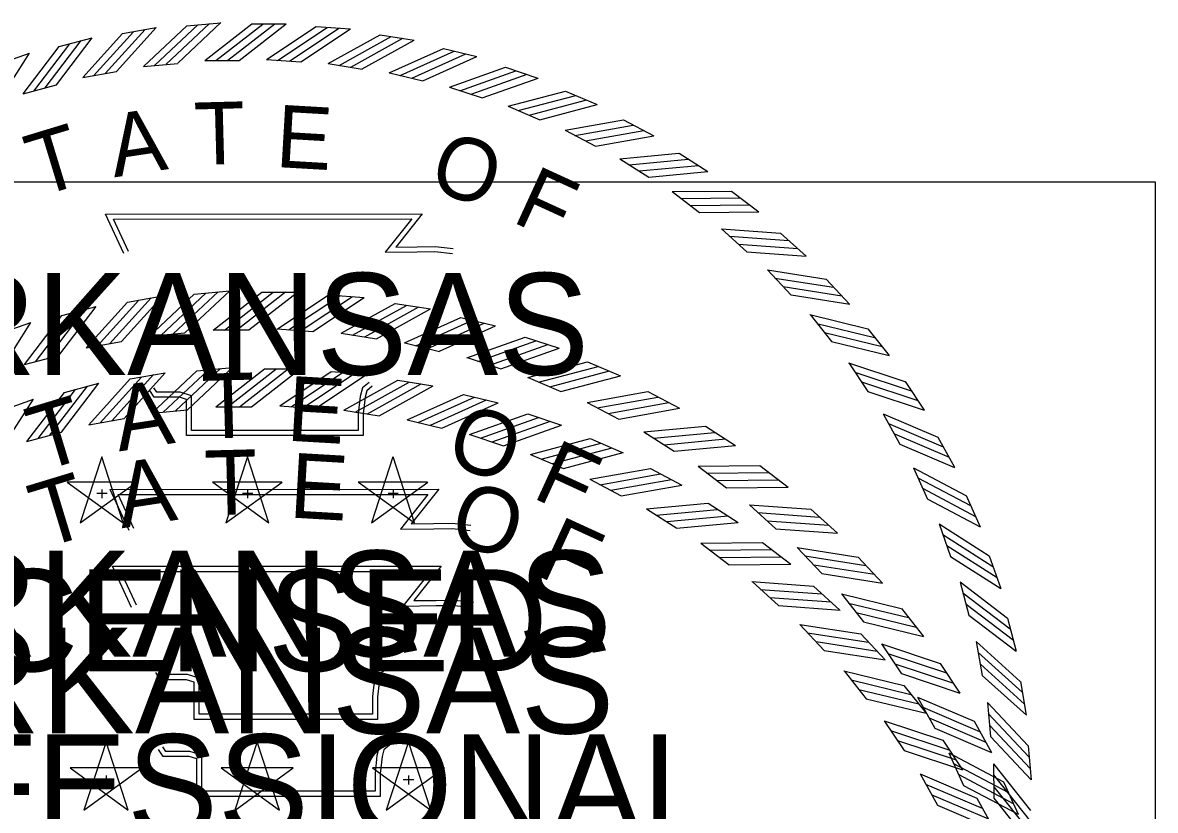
# Model space of a CAD drawing. Extents: x 0 to 1228740, y 0 to 152440.
# Drawn here: x 31.694 to 33.423, y 24.476 to 25.678 of the extents above; entities that cross this region are included whole.
import ezdxf

# ---------------------------------------------------------------- set-up
doc = ezdxf.new("R2010")
doc.units = 0
for name, color, linetype in [('R_No Plot', 7, 'Continuous'), ('STAMP_LKM', 7, 'Continuous'), ('STAMP_PP', 7, 'Continuous'), ('STAMP_SPT', 7, 'Continuous')]:
    doc.layers.add(name, color=color, linetype=linetype)

msp = doc.modelspace()

# ---------------------------------------------------------------- linework, layer by layer
at = {"layer": 'R_No Plot'}
msp.add_lwpolyline([(30.6731, 25.4352), (33.4231, 25.4352), (33.4231, 22.6852), (30.6731, 22.6852)], close=True, dxfattribs=at)
at = {"layer": 'STAMP_LKM'}
for p, q in [((31.8544, 25.2516), (31.9079, 25.2611)), ((31.9562, 25.2638), (32.0104, 25.2688)), ((32.0592, 25.2669), (32.1136, 25.2669)), ((32.1611, 25.2628), (32.2154, 25.2588)), ((31.7539, 25.2311), (31.8065, 25.245)), ((32.2628, 25.2496), (32.3166, 25.2411)), ((32.3631, 25.228), (32.416, 25.2151)), ((31.6554, 25.2024), (31.7067, 25.2205)), ((31.985, 25.209), (32.0395, 25.209)), ((32.0828, 25.2105), (32.1372, 25.2065)), ((31.7913, 25.1817), (31.845, 25.1912)), ((31.8876, 25.1994), (31.9419, 25.2044)), ((32.1805, 25.2039), (32.2344, 25.1954)), ((32.4613, 25.1982), (32.5129, 25.181)), ((32.2773, 25.1893), (32.3303, 25.1764)), ((31.6968, 25.1562), (31.7495, 25.1701)), ((32.3725, 25.1668), (32.4243, 25.1495)), ((32.5566, 25.1605), (32.6066, 25.1391)), ((32.4656, 25.1364), (32.5157, 25.115)), ((32.6485, 25.115), (32.6966, 25.0895)), ((32.5558, 25.0985), (32.604, 25.073)), ((32.6426, 25.0533), (32.6885, 25.0239)), ((32.7364, 25.062), (32.7822, 25.0327)), ((32.7254, 25.001), (32.7687, 24.9679)), ((32.8195, 25.002), (32.8628, 24.969)), ((32.8035, 24.9421), (32.844, 24.9056)), ((32.8974, 24.9353), (32.9378, 24.8988)), ((32.8766, 24.877), (32.9139, 24.8372)), ((32.9696, 24.8624), (33.0068, 24.8227)), ((32.944, 24.806), (32.9779, 24.7633)), ((33.0355, 24.7838), (33.0693, 24.7412)), ((33.0053, 24.7297), (33.0355, 24.6843)), ((33.0946, 24.7001), (33.1248, 24.6548)), ((33.0601, 24.6486), (33.0865, 24.6009)), ((33.1467, 24.6117), (33.173, 24.5641)), ((31.8215, 24.5804), (31.7874, 24.476)), ((31.8554, 24.476), (31.8215, 24.5805)), ((32.0523, 24.5804), (32.0182, 24.476)), ((32.0862, 24.476), (32.0523, 24.5805)), ((32.283, 24.5804), (32.249, 24.476)), ((32.317, 24.476), (32.2831, 24.5805)), ((33.108, 24.5633), (33.1304, 24.5135)), ((31.8763, 24.5405), (31.7665, 24.5406)), ((31.7666, 24.5405), (31.8554, 24.4759)), ((31.7876, 24.476), (31.8765, 24.5405)), ((32.1071, 24.5405), (31.9973, 24.5406)), ((31.9974, 24.5405), (32.0862, 24.4759)), ((32.0183, 24.476), (32.1073, 24.5405)), ((32.3379, 24.5405), (32.2281, 24.5406)), ((32.2282, 24.5405), (32.317, 24.4759)), ((32.2491, 24.476), (32.338, 24.5405)), ((31.8137, 24.523), (31.83, 24.523)), ((31.8216, 24.5288), (31.8216, 24.5151)), ((32.0444, 24.523), (32.0608, 24.523)), ((32.0524, 24.5288), (32.0524, 24.5151)), ((32.2752, 24.523), (32.2915, 24.523)), ((32.2831, 24.5288), (32.2831, 24.5151)), ((33.1913, 24.5193), (33.2136, 24.4697))]:
    msp.add_line(p, q, dxfattribs=at)
for points in [[(31.8449, 25.1912), (31.908, 25.2611)], [(31.8875, 25.1993), (31.9561, 25.2638)], [(31.905, 25.2007), (31.9736, 25.2652)], [(31.9238, 25.2029), (31.9924, 25.2674)], [(31.9418, 25.2044), (32.0104, 25.2689)], [(31.9849, 25.2089), (32.0592, 25.2668)], [(32.0024, 25.2087), (32.0767, 25.2666)], [(32.0213, 25.2092), (32.0956, 25.2671)], [(32.0395, 25.209), (32.1137, 25.2669)], [(32.0828, 25.2104), (32.1611, 25.2627)], [(32.1002, 25.209), (32.1785, 25.2613)], [(32.1191, 25.208), (32.1974, 25.2603)], [(31.7495, 25.1701), (31.8065, 25.245)], [(31.7912, 25.1817), (31.8543, 25.2516)], [(31.8085, 25.1846), (31.8716, 25.2545)], [(31.8271, 25.1883), (31.8901, 25.2582)], [(32.1372, 25.2065), (32.2155, 25.2588)], [(32.1804, 25.2039), (32.2628, 25.2495)], [(32.1977, 25.201), (32.28, 25.2466)], [(32.2164, 25.1985), (32.2988, 25.2441)], [(31.6968, 25.1562), (31.7538, 25.231)], [(31.7137, 25.1605), (31.7708, 25.2353)], [(31.7319, 25.1657), (31.789, 25.2406)], [(32.2343, 25.1955), (32.3166, 25.2411)], [(32.2772, 25.1893), (32.363, 25.228)], [(31.6561, 25.1412), (31.7068, 25.2205)], [(32.2942, 25.185), (32.38, 25.2237)], [(32.3126, 25.1809), (32.3985, 25.2196)], [(32.3302, 25.1765), (32.416, 25.2152)], [(32.3724, 25.1667), (32.4612, 25.1982)], [(32.389, 25.1611), (32.4777, 25.1925)], [(32.4071, 25.1555), (32.4958, 25.187)], [(32.4242, 25.1496), (32.5129, 25.1811)], [(32.4655, 25.1364), (32.5565, 25.1605)], [(32.4815, 25.1294), (32.5726, 25.1534)], [(32.4991, 25.1223), (32.5901, 25.1464)], [(32.5157, 25.1151), (32.6067, 25.1391)], [(32.5557, 25.0985), (32.6484, 25.115)], [(32.5711, 25.0902), (32.6638, 25.1066)], [(32.588, 25.0817), (32.6807, 25.0981)], [(32.604, 25.0731), (32.6967, 25.0895)], [(32.6425, 25.0533), (32.7363, 25.062)], [(32.6572, 25.0437), (32.7509, 25.0524)], [(32.6733, 25.0339), (32.7671, 25.0426)], [(32.6885, 25.024), (32.7822, 25.0327)], [(32.7253, 25.001), (32.8194, 25.002)], [(32.7391, 24.9903), (32.8332, 24.9912)], [(32.7544, 24.9791), (32.8485, 24.9801)], [(32.7687, 24.968), (32.8628, 24.969)], [(31.8565, 24.9027), (31.8275, 24.9655), (32.3293, 24.9658), (32.2874, 24.9131), (32.3215, 24.9136), (32.3499, 24.9139), (32.3784, 24.9108)], [(31.8637, 24.906), (31.8399, 24.9576), (32.3128, 24.9579), (32.2707, 24.905), (32.3216, 24.9056), (32.3496, 24.906), (32.3775, 24.9029)], [(32.8035, 24.9421), (32.8973, 24.9353)], [(32.8163, 24.9303), (32.9102, 24.9235)], [(32.8306, 24.9179), (32.9245, 24.9111)], [(32.844, 24.9056), (32.9379, 24.8988)], [(32.8765, 24.877), (32.9695, 24.8624)], [(32.8883, 24.8641), (32.9814, 24.8496)], [(32.9016, 24.8506), (32.9946, 24.8361)], [(32.9139, 24.8373), (33.0069, 24.8227)], [(32.9439, 24.806), (33.0354, 24.7839)], [(32.9546, 24.7922), (33.0461, 24.77)], [(32.9667, 24.7777), (33.0582, 24.7555)], [(32.9779, 24.7634), (33.0693, 24.7412)], [(33.0052, 24.7297), (33.0946, 24.7001)], [(33.0148, 24.7151), (33.1041, 24.6854)], [(32.2502, 24.6924), (32.2417, 24.6855), (32.2388, 24.6751), (32.236, 24.649), (32.236, 24.6144), (31.9559, 24.6144), (31.9559, 24.6612), (31.9559, 24.6716), (31.9445, 24.6751), (31.9047, 24.6751), (31.8976, 24.6859)], [(32.2452, 24.6986), (32.2347, 24.69), (32.231, 24.6765), (32.2281, 24.6495), (32.2281, 24.6223), (31.9638, 24.6223), (31.9638, 24.6612), (31.9638, 24.6775), (31.9457, 24.683), (31.909, 24.683), (31.9042, 24.6902)], [(33.0256, 24.6996), (33.115, 24.6699)], [(33.0355, 24.6844), (33.1249, 24.6548)], [(33.06, 24.6487), (33.1466, 24.6117)], [(33.0683, 24.6333), (33.1549, 24.5963)], [(33.0779, 24.6169), (33.1645, 24.58)], [(33.0865, 24.601), (33.1731, 24.564)], [(33.1079, 24.5633), (33.1912, 24.5194)], [(33.115, 24.5473), (33.1982, 24.5033)], [(33.1231, 24.5302), (33.2063, 24.4863)], [(33.1304, 24.5136), (33.2136, 24.4697)]]:
    msp.add_lwpolyline(points, dxfattribs=at)
at = {"layer": 'STAMP_PP'}
for p, q in [((31.9447, 25.6733), (31.9968, 25.6781)), ((32.0439, 25.6762), (32.0963, 25.6762)), ((31.8466, 25.6616), (31.8982, 25.6707)), ((32.142, 25.6723), (32.1943, 25.6685)), ((32.24, 25.6596), (32.2918, 25.6514)), ((31.7498, 25.6418), (31.8005, 25.6551)), ((31.655, 25.6141), (31.7044, 25.6316)), ((32.3366, 25.6388), (32.3875, 25.6264)), ((31.8786, 25.6112), (31.9309, 25.616)), ((31.9724, 25.6205), (32.0249, 25.6205)), ((32.0666, 25.6219), (32.119, 25.6181)), ((32.1607, 25.6156), (32.2126, 25.6074)), ((32.4311, 25.6101), (32.4808, 25.5936)), ((31.7858, 25.5943), (31.8376, 25.6034)), ((32.2539, 25.6016), (32.3049, 25.5891)), ((31.6948, 25.5697), (31.7456, 25.5831)), ((32.3456, 25.5798), (32.3955, 25.5632)), ((32.5229, 25.5738), (32.5711, 25.5532)), ((32.4353, 25.5506), (32.4836, 25.53)), ((32.6115, 25.5299), (32.6578, 25.5054)), ((32.5222, 25.5141), (32.5686, 25.4895)), ((32.6058, 25.4705), (32.65, 25.4422)), ((32.6961, 25.4789), (32.7402, 25.4507)), ((32.6855, 25.4202), (32.7272, 25.3883)), ((32.7762, 25.4211), (32.8178, 25.3893)), ((32.7608, 25.3635), (32.7997, 25.3283)), ((32.8512, 25.3569), (32.8901, 25.3218)), ((32.8311, 25.3007), (32.867, 25.2624)), ((32.9207, 25.2867), (32.9565, 25.2485)), ((32.896, 25.2324), (32.9287, 25.1912)), ((32.9841, 25.211), (33.0167, 25.17)), ((32.9551, 25.1589), (32.9842, 25.1152)), ((33.0411, 25.1303), (33.0702, 25.0867)), ((33.0079, 25.0808), (33.0333, 25.0348)), ((33.0913, 25.0452), (33.1166, 24.9994)), ((31.8149, 25.0151), (31.7821, 24.9145)), ((31.8476, 24.9145), (31.815, 25.0152)), ((32.0372, 25.0151), (32.0044, 24.9145)), ((32.0698, 24.9145), (32.0372, 25.0152)), ((32.2594, 25.0151), (32.2267, 24.9145)), ((32.2921, 24.9145), (32.2595, 25.0152)), ((33.054, 24.9986), (33.0755, 24.9507)), ((31.8678, 24.9767), (31.762, 24.9768)), ((31.7621, 24.9767), (31.8476, 24.9144)), ((31.7822, 24.9145), (31.8679, 24.9766)), ((32.09, 24.9767), (31.9842, 24.9768)), ((31.9843, 24.9767), (32.0699, 24.9144)), ((32.0045, 24.9145), (32.0902, 24.9766)), ((32.3123, 24.9767), (32.2065, 24.9768)), ((32.2066, 24.9767), (32.2921, 24.9144)), ((32.2268, 24.9145), (32.3124, 24.9766)), ((31.8074, 24.9598), (31.8231, 24.9598)), ((31.815, 24.9654), (31.815, 24.9521)), ((32.0296, 24.9598), (32.0454, 24.9598)), ((32.0373, 24.9654), (32.0373, 24.9521)), ((32.2519, 24.9598), (32.2676, 24.9598)), ((32.2595, 24.9654), (32.2595, 24.9521)), ((33.1342, 24.9562), (33.1557, 24.9085)), ((33.0932, 24.9129), (33.1107, 24.8634)), ((33.1696, 24.864), (33.1871, 24.8146)), ((33.1252, 24.8242), (33.1386, 24.7734)), ((33.1973, 24.7692), (33.2107, 24.7186)), ((33.1498, 24.7332), (33.1589, 24.6815)), ((33.2171, 24.6725), (33.2262, 24.6208)), ((33.1667, 24.6405), (33.1716, 24.5882)), ((33.2288, 24.5744), (33.2336, 24.5222)), ((33.176, 24.5467), (33.1765, 24.4941))]:
    msp.add_line(p, q, dxfattribs=at)
for points in [[(31.9134, 25.6146), (31.9795, 25.6767)], [(31.9308, 25.6161), (31.9969, 25.6782)], [(31.9723, 25.6204), (32.0438, 25.6762)], [(31.9892, 25.6203), (32.0607, 25.676)], [(32.0074, 25.6207), (32.0789, 25.6764)], [(32.0248, 25.6205), (32.0963, 25.6763)], [(31.7858, 25.5942), (31.8465, 25.6615)], [(31.8024, 25.597), (31.8632, 25.6643)], [(31.8203, 25.6005), (31.881, 25.6679)], [(31.8375, 25.6034), (31.8982, 25.6707)], [(31.8785, 25.6112), (31.9446, 25.6733)], [(31.8953, 25.6126), (31.9614, 25.6746)], [(32.0666, 25.6219), (32.142, 25.6723)], [(32.0834, 25.6205), (32.1588, 25.6709)], [(32.1016, 25.6196), (32.177, 25.6699)], [(32.119, 25.6181), (32.1944, 25.6685)], [(32.1606, 25.6156), (32.2399, 25.6595)], [(31.6948, 25.5696), (31.7497, 25.6417)], [(31.7111, 25.5738), (31.7661, 25.6459)], [(31.7286, 25.5788), (31.7836, 25.6509)], [(31.7456, 25.5831), (31.8005, 25.6552)], [(32.1773, 25.6128), (32.2566, 25.6568)], [(32.1953, 25.6104), (32.2746, 25.6543)], [(32.2125, 25.6075), (32.2918, 25.6515)], [(31.6556, 25.5552), (31.7044, 25.6316)], [(32.2538, 25.6015), (32.3365, 25.6388)], [(32.2702, 25.5974), (32.3528, 25.6346)], [(32.288, 25.5935), (32.3706, 25.6307)], [(32.3049, 25.5892), (32.3875, 25.6264)], [(32.3456, 25.5798), (32.431, 25.6101)], [(32.3615, 25.5743), (32.447, 25.6046)], [(32.3789, 25.569), (32.4644, 25.5993)], [(32.3954, 25.5633), (32.4809, 25.5936)], [(32.4352, 25.5506), (32.5228, 25.5738)], [(32.4506, 25.5438), (32.5383, 25.567)], [(32.4675, 25.537), (32.5552, 25.5602)], [(32.4835, 25.53), (32.5712, 25.5532)], [(32.5221, 25.5141), (32.6114, 25.5299)], [(32.5369, 25.5061), (32.6262, 25.5219)], [(32.5532, 25.4979), (32.6425, 25.5137)], [(32.5686, 25.4896), (32.6578, 25.5054)], [(32.6057, 25.4705), (32.696, 25.4789)], [(32.6198, 25.4613), (32.7101, 25.4697)], [(32.6354, 25.4518), (32.7256, 25.4602)], [(32.65, 25.4423), (32.7402, 25.4507)], [(32.6854, 25.4202), (32.7761, 25.4211)], [(32.6987, 25.4099), (32.7894, 25.4108)], [(32.7134, 25.3991), (32.8041, 25.4001)], [(31.8487, 25.3255), (31.8207, 25.386), (32.304, 25.3863), (32.2636, 25.3355), (32.2965, 25.336), (32.3239, 25.3363), (32.3513, 25.3333)], [(32.7272, 25.3884), (32.8179, 25.3893)], [(31.8556, 25.3287), (31.8327, 25.3784), (32.2881, 25.3786), (32.2476, 25.3277), (32.2966, 25.3283), (32.3235, 25.3287), (32.3505, 25.3257)], [(32.7607, 25.3635), (32.8511, 25.3569)], [(32.7731, 25.3521), (32.8635, 25.3455)], [(32.7869, 25.3402), (32.8773, 25.3336)], [(32.7997, 25.3283), (32.8901, 25.3218)], [(32.831, 25.3007), (32.9206, 25.2867)], [(32.8424, 25.2883), (32.932, 25.2743)], [(32.8552, 25.2753), (32.9448, 25.2613)], [(32.867, 25.2625), (32.9566, 25.2485)], [(32.8959, 25.2324), (32.9841, 25.211)], [(32.9063, 25.2191), (32.9944, 25.1977)], [(32.9179, 25.2051), (33.006, 25.1837)], [(32.9287, 25.1913), (33.0168, 25.1699)], [(32.955, 25.1589), (33.041, 25.1304)], [(32.9642, 25.1448), (33.0503, 25.1162)], [(32.2279, 25.123), (32.2196, 25.1163), (32.2169, 25.1063), (32.2141, 25.0812), (32.2141, 25.0478), (31.9444, 25.0478), (31.9444, 25.0929), (31.9444, 25.1029), (31.9334, 25.1063), (31.895, 25.1063), (31.8882, 25.1167)], [(32.223, 25.1289), (32.2129, 25.1207), (32.2093, 25.1077), (32.2065, 25.0816), (32.2065, 25.0554), (31.952, 25.0554), (31.952, 25.0929), (31.952, 25.1086), (31.9346, 25.1139), (31.8992, 25.1139), (31.8946, 25.1209)], [(32.9747, 25.1299), (33.0607, 25.1013)], [(32.9842, 25.1153), (33.0703, 25.0867)], [(33.0078, 25.0808), (33.0912, 25.0453)], [(33.0158, 25.066), (33.0992, 25.0304)], [(33.025, 25.0503), (33.1084, 25.0147)], [(33.0333, 25.0349), (33.1167, 24.9993)], [(33.0539, 24.9986), (33.1341, 24.9563)], [(33.0607, 24.9832), (33.1409, 24.9409)], [(33.0685, 24.9668), (33.1487, 24.9244)], [(33.0756, 24.9508), (33.1557, 24.9084)], [(33.0931, 24.9129), (33.1696, 24.8641)], [(33.0986, 24.897), (33.175, 24.8481)], [(33.1051, 24.8799), (33.1815, 24.8311)], [(33.1107, 24.8634), (33.1872, 24.8146)], [(33.1251, 24.8243), (33.1973, 24.7693)], [(33.1293, 24.8079), (33.2014, 24.7529)], [(33.1343, 24.7904), (33.2064, 24.7354)], [(33.1386, 24.7735), (33.2107, 24.7185)], [(33.1497, 24.7332), (33.217, 24.6725)], [(33.1525, 24.7166), (33.2198, 24.6559)], [(33.156, 24.6988), (33.2234, 24.638)], [(33.1589, 24.6815), (33.2263, 24.6208)], [(33.1667, 24.6405), (33.2288, 24.5744)], [(33.1681, 24.6237), (33.2302, 24.5576)], [(33.1701, 24.6056), (33.2322, 24.5395)], [(33.1716, 24.5882), (33.2337, 24.5221)], [(33.1759, 24.5467), (33.2324, 24.4757)], [(33.1759, 24.5298), (33.2324, 24.4589)], [(33.1765, 24.5116), (33.2329, 24.4407)], [(33.1765, 24.4942), (33.2329, 24.4232)]]:
    msp.add_lwpolyline(points, dxfattribs=at)
at = {"layer": 'STAMP_SPT'}
for p, q in [((31.8583, 25.1343), (31.9119, 25.1438)), ((31.9601, 25.1465), (32.0143, 25.1515)), ((32.0632, 25.1495), (32.1176, 25.1495)), ((32.1651, 25.1454), (32.2193, 25.1414)), ((31.7578, 25.1138), (31.8104, 25.1276)), ((32.2668, 25.1322), (32.3205, 25.1238)), ((32.367, 25.1107), (32.4199, 25.0978)), ((31.6594, 25.085), (31.7107, 25.1032)), ((31.9889, 25.0916), (32.0435, 25.0916)), ((32.0868, 25.0931), (32.1412, 25.0891)), ((31.7952, 25.0644), (31.8489, 25.0739)), ((31.8915, 25.082), (31.9458, 25.087)), ((32.1844, 25.0866), (32.2383, 25.0781)), ((32.2812, 25.072), (32.3342, 25.0591)), ((32.4652, 25.0809), (32.5168, 25.0637)), ((31.7007, 25.0389), (31.7535, 25.0528)), ((32.3765, 25.0494), (32.4282, 25.0322)), ((32.5605, 25.0431), (32.6106, 25.0217)), ((32.4695, 25.0191), (32.5197, 24.9977)), ((32.6525, 24.9976), (32.7005, 24.9722)), ((32.5597, 24.9812), (32.6079, 24.9557)), ((32.6465, 24.9359), (32.6925, 24.9065)), ((32.7403, 24.9447), (32.7861, 24.9153)), ((32.7293, 24.8837), (32.7726, 24.8506)), ((32.8235, 24.8847), (32.8667, 24.8516)), ((32.8075, 24.8248), (32.8479, 24.7882)), ((32.9014, 24.818), (32.9417, 24.7815)), ((32.8805, 24.7596), (32.9178, 24.7199)), ((32.9735, 24.7451), (33.0107, 24.7054)), ((32.9479, 24.6887), (32.9818, 24.6459)), ((33.0394, 24.6665), (33.0732, 24.6239)), ((33.0092, 24.6124), (33.0395, 24.567)), ((33.0986, 24.5827), (33.1288, 24.5374)), ((33.064, 24.5313), (33.0904, 24.4836)), ((33.1506, 24.4943), (33.177, 24.4467))]:
    msp.add_line(p, q, dxfattribs=at)
for points in [[(31.831, 25.0709), (31.894, 25.1408)], [(31.8489, 25.0739), (31.9119, 25.1438)], [(31.8915, 25.082), (31.9601, 25.1464)], [(31.9089, 25.0834), (31.9775, 25.1479)], [(31.9277, 25.0856), (31.9963, 25.15)], [(31.9458, 25.087), (32.0144, 25.1515)], [(31.9889, 25.0916), (32.0631, 25.1495)], [(32.0064, 25.0914), (32.0806, 25.1493)], [(32.0253, 25.0918), (32.0995, 25.1497)], [(32.0434, 25.0917), (32.1176, 25.1495)], [(32.0867, 25.0931), (32.165, 25.1454)], [(32.1042, 25.0916), (32.1824, 25.1439)], [(32.123, 25.0907), (32.2013, 25.143)], [(32.1411, 25.0892), (32.2194, 25.1415)], [(31.7358, 25.0483), (31.7929, 25.1232)], [(31.7534, 25.0528), (31.8105, 25.1277)], [(31.7952, 25.0643), (31.8582, 25.1342)], [(31.8125, 25.0672), (31.8755, 25.1371)], [(32.1844, 25.0865), (32.2667, 25.1322)], [(32.2016, 25.0837), (32.284, 25.1293)], [(32.2204, 25.0811), (32.3027, 25.1268)], [(32.2382, 25.0781), (32.3206, 25.1238)], [(31.7007, 25.0388), (31.7578, 25.1137)], [(31.7177, 25.0431), (31.7747, 25.118)], [(32.2811, 25.0719), (32.367, 25.1106)], [(32.2981, 25.0676), (32.3839, 25.1063)], [(31.66, 25.0239), (31.7107, 25.1032)], [(32.3166, 25.0636), (32.4024, 25.1023)], [(32.3341, 25.0591), (32.42, 25.0978)], [(32.3764, 25.0494), (32.4651, 25.0809)], [(32.3929, 25.0437), (32.4817, 25.0752)], [(32.411, 25.0381), (32.4997, 25.0696)], [(32.4281, 25.0323), (32.5169, 25.0637)], [(32.4694, 25.0191), (32.5605, 25.0431)], [(32.4855, 25.012), (32.5765, 25.0361)], [(32.503, 25.005), (32.594, 25.029)], [(32.5196, 24.9977), (32.6106, 25.0218)], [(32.5597, 24.9812), (32.6524, 24.9976)], [(32.5751, 24.9728), (32.6678, 24.9893)], [(32.592, 24.9644), (32.6847, 24.9808)], [(32.6079, 24.9557), (32.7006, 24.9722)], [(32.6465, 24.9359), (32.7402, 24.9447)], [(32.6611, 24.9264), (32.7549, 24.9351)], [(32.6773, 24.9165), (32.771, 24.9253)], [(32.6924, 24.9066), (32.7862, 24.9153)], [(32.7292, 24.8837), (32.8234, 24.8847)], [(32.743, 24.8729), (32.8372, 24.8739)], [(32.7583, 24.8618), (32.8525, 24.8628)], [(31.8605, 24.7854), (31.8315, 24.8482), (32.3332, 24.8485), (32.2913, 24.7958), (32.3254, 24.7962), (32.3539, 24.7966), (32.3823, 24.7935)], [(32.7726, 24.8507), (32.8668, 24.8516)], [(31.8677, 24.7887), (31.8439, 24.8402), (32.3168, 24.8405), (32.2747, 24.7876), (32.3255, 24.7883), (32.3535, 24.7886), (32.3815, 24.7856)], [(32.8074, 24.8248), (32.9013, 24.818)], [(32.8203, 24.8129), (32.9142, 24.8061)], [(32.8346, 24.8006), (32.9285, 24.7938)], [(32.8479, 24.7883), (32.9418, 24.7815)], [(32.8804, 24.7596), (32.9734, 24.7451)], [(32.8923, 24.7468), (32.9853, 24.7322)], [(32.9055, 24.7333), (32.9985, 24.7187)], [(32.9178, 24.7199), (33.0108, 24.7054)], [(32.9478, 24.6887), (33.0393, 24.6665)], [(32.9586, 24.6749), (33.0501, 24.6527)], [(32.9707, 24.6603), (33.0621, 24.6381)], [(32.9818, 24.646), (33.0733, 24.6238)], [(33.0091, 24.6124), (33.0985, 24.5827)], [(33.0187, 24.5977), (33.1081, 24.5681)], [(32.2542, 24.5751), (32.2456, 24.5681), (32.2428, 24.5577), (32.2399, 24.5317), (32.2399, 24.497), (31.9598, 24.497), (31.9598, 24.5438), (31.9598, 24.5542), (31.9485, 24.5577), (31.9086, 24.5577), (31.9015, 24.5685)], [(32.2492, 24.5813), (32.2386, 24.5727), (32.2349, 24.5592), (32.232, 24.5321), (32.232, 24.505), (31.9678, 24.505), (31.9678, 24.5438), (31.9678, 24.5601), (31.9496, 24.5657), (31.9129, 24.5657), (31.9082, 24.5729)], [(33.0296, 24.5823), (33.1189, 24.5526)], [(33.0395, 24.5671), (33.1288, 24.5374)], [(33.0639, 24.5313), (33.1505, 24.4944)], [(33.0723, 24.5159), (33.1589, 24.479)], [(33.0818, 24.4996), (33.1684, 24.4626)], [(33.0904, 24.4836), (33.177, 24.4467)]]:
    msp.add_lwpolyline(points, dxfattribs=at)

# ---------------------------------------------------------------- texts
at = {"layer": 'STAMP_LKM'}
for s, rotation, p in [('T', 1.4789, (31.969, 25.0432)), ('A', 8.6788, (31.8412, 25.0235)), ('E', 356.672, (32.0957, 25.0402)), ('T', 16.9015, (31.721, 24.9921)), ('O', 341.2218, (32.3361, 25.0063)), ('F', 335.3628, (32.4695, 24.9541))]:
    msp.add_text(s, height=0.099, rotation=rotation, dxfattribs=at).set_placement(p)
msp.add_text('ARKANSAS', height=0.16155, dxfattribs=at).set_placement((31.4173, 24.7105))
at = {"layer": 'STAMP_PP'}
for s, rotation, p in [('T', 1.4789, (31.957, 25.4608)), ('A', 8.6788, (31.8339, 25.4419)), ('E', 356.672, (32.079, 25.4579)), ('T', 16.9015, (31.7182, 25.4116)), ('O', 341.2218, (32.3105, 25.4252)), ('F', 335.3628, (32.439, 25.375))]:
    msp.add_text(s, height=0.0953, rotation=rotation, dxfattribs=at).set_placement(p)
for s, height, p in [('ARKANSAS', 0.15559, (31.4257, 25.1404)), ('LICENSED', 0.15559, (31.4553, 24.6881)), ('PROFESSIONAL', 0.155591, (31.1367, 24.4362))]:
    msp.add_text(s, height=height, dxfattribs=at).set_placement(p)
at = {"layer": 'STAMP_SPT'}
for s, rotation, p in [('T', 1.4789, (31.973, 24.9259)), ('E', 356.672, (32.0997, 24.9229)), ('A', 8.6788, (31.8452, 24.9062)), ('T', 16.9015, (31.725, 24.8748)), ('O', 341.2218, (32.34, 24.8889)), ('F', 335.3628, (32.4734, 24.8367))]:
    msp.add_text(s, height=0.099, rotation=rotation, dxfattribs=at).set_placement(p)
msp.add_text('ARKANSAS', height=0.16155, dxfattribs=at).set_placement((31.4213, 24.5931))

doc.saveas('drawing.dxf')
